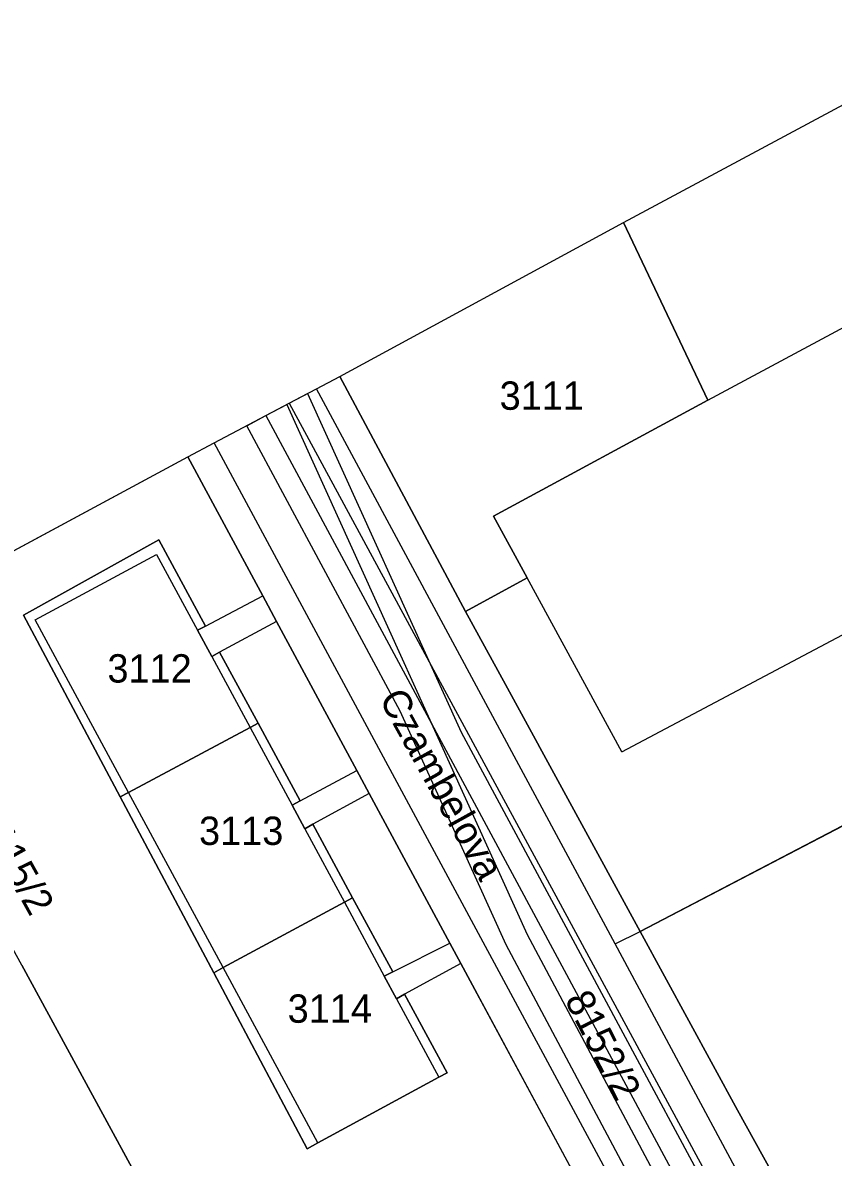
# Model space of a CAD drawing. Extents: x -264070 to -262271, y -1238894 to -1238141.
# Drawn here: x -263175.7 to -263118.5, y -1238393.6 to -1238313.6 of the extents above; entities that cross this region are included whole.
import ezdxf

# ---------------------------------------------------------------- set-up
doc = ezdxf.new("R2010")
doc.units = 0
for name, color, linetype in [('body_kn', 7, 'Continuous'), ('katuz_linie', 7, 'Continuous'), ('kladpar_druhypozemkov', 7, 'Continuous'), ('kladpar_hranice', 7, 'Continuous'), ('kladpar_parcelnecisla', 7, 'Continuous'), ('kladpar_plochy', 7, 'Continuous'), ('popisy', 7, 'Continuous'), ('tarchy_linie', 7, 'Continuous'), ('zappar_hrandruhpozemk', 7, 'Continuous'), ('zuob_linie', 7, 'Continuous'), ('zuob_plochy', 7, 'Continuous')]:
    doc.layers.add(name, color=color, linetype=linetype)

msp = doc.modelspace()

# ---------------------------------------------------------------- linework, layer by layer
at = {"layer": 'body_kn'}
for p, q in [((-263133.32, -1238327.67), (-263133.32, -1238327.67)), ((-263133.32, -1238327.67), (-263133.32, -1238327.67)), ((-263153.35, -1238338.53), (-263153.35, -1238338.53)), ((-263155.61, -1238339.73), (-263155.61, -1238339.73)), ((-263154.99, -1238339.4), (-263154.99, -1238339.4)), ((-263157.07, -1238340.51), (-263157.07, -1238340.51)), ((-263157.07, -1238340.51), (-263157.07, -1238340.51)), ((-263156.91, -1238340.42), (-263156.91, -1238340.42)), ((-263156.91, -1238340.42), (-263156.91, -1238340.42)), ((-263127.36, -1238340.2), (-263127.36, -1238340.2)), ((-263127.36, -1238340.2), (-263127.36, -1238340.2)), ((-263158.55, -1238341.29), (-263158.55, -1238341.29)), ((-263158.55, -1238341.29), (-263158.55, -1238341.29)), ((-263159.91, -1238342.01), (-263159.91, -1238342.01)), ((-263162.21, -1238343.23), (-263162.21, -1238343.23)), ((-263164.06, -1238344.21), (-263164.06, -1238344.21)), ((-263142.5, -1238348.4), (-263142.5, -1238348.4)), ((-263166.11, -1238350.06), (-263166.11, -1238350.06)), ((-263166.11, -1238350.06), (-263166.11, -1238350.06)), ((-263166.27, -1238351.1), (-263166.27, -1238351.1)), ((-263166.27, -1238351.1), (-263166.27, -1238351.1)), ((-263140.13, -1238352.75), (-263140.13, -1238352.75)), ((-263158.78, -1238354.03), (-263158.78, -1238354.03)), ((-263175.66, -1238355.38), (-263175.66, -1238355.38)), ((-263174.83, -1238355.72), (-263174.83, -1238355.72)), ((-263157.81, -1238355.82), (-263157.81, -1238355.82)), ((-263157.81, -1238355.82), (-263157.81, -1238355.82)), ((-263144.47, -1238355.12), (-263144.47, -1238355.12)), ((-263163.38, -1238356.45), (-263163.38, -1238356.45)), ((-263162.81, -1238356.16), (-263162.81, -1238356.16)), ((-263162.81, -1238356.16), (-263162.81, -1238356.16)), ((-263161.82, -1238358), (-263161.82, -1238358)), ((-263162.37, -1238358.31), (-263162.37, -1238358.31)), ((-263162.37, -1238358.31), (-263162.37, -1238358.31)), ((-263141.66, -1238360.28), (-263141.66, -1238360.28)), ((-263149.08, -1238362.16), (-263149.08, -1238362.16)), ((-263159.11, -1238363.01), (-263159.11, -1238363.01)), ((-263159.67, -1238363.31), (-263159.67, -1238363.31)), ((-263159.67, -1238363.31), (-263159.67, -1238363.31)), ((-263144.78, -1238363.64), (-263144.78, -1238363.64)), ((-263133.43, -1238365.04), (-263133.43, -1238365.04)), ((-263152.15, -1238366.34), (-263152.15, -1238366.34)), ((-263168.83, -1238368.21), (-263168.83, -1238368.21)), ((-263168.25, -1238367.89), (-263168.25, -1238367.89)), ((-263168.25, -1238367.89), (-263168.25, -1238367.89)), ((-263156.13, -1238368.49), (-263156.13, -1238368.49)), ((-263156.13, -1238368.49), (-263156.13, -1238368.49)), ((-263151.26, -1238367.98), (-263151.26, -1238367.98)), ((-263151.26, -1238367.98), (-263151.26, -1238367.98)), ((-263156.71, -1238368.8), (-263156.71, -1238368.8)), ((-263155.24, -1238370.14), (-263155.24, -1238370.14)), ((-263155.81, -1238370.46), (-263155.81, -1238370.46)), ((-263155.81, -1238370.46), (-263155.81, -1238370.46)), ((-263153.02, -1238375.64), (-263153.02, -1238375.64)), ((-263153.02, -1238375.64), (-263153.02, -1238375.64)), ((-263152.44, -1238375.33), (-263152.44, -1238375.33)), ((-263140.13, -1238377.91), (-263140.13, -1238377.91)), ((-263132.14, -1238377.71), (-263132.14, -1238377.71)), ((-263132.14, -1238377.71), (-263132.14, -1238377.71)), ((-263145.58, -1238378.53), (-263145.58, -1238378.53)), ((-263141.61, -1238378.64), (-263141.61, -1238378.64)), ((-263133.92, -1238378.58), (-263133.92, -1238378.58)), ((-263133.92, -1238378.58), (-263133.92, -1238378.58)), ((-263162.24, -1238380.62), (-263162.24, -1238380.62)), ((-263161.58, -1238380.25), (-263161.58, -1238380.25)), ((-263161.58, -1238380.25), (-263161.58, -1238380.25)), ((-263149.61, -1238380.56), (-263149.61, -1238380.56)), ((-263149.61, -1238380.56), (-263149.61, -1238380.56)), ((-263144.81, -1238379.96), (-263144.81, -1238379.96)), ((-263144.81, -1238379.96), (-263144.81, -1238379.96)), ((-263150.2, -1238380.87), (-263150.2, -1238380.87)), ((-263148.77, -1238382.13), (-263148.77, -1238382.13)), ((-263149.34, -1238382.45), (-263149.34, -1238382.45)), ((-263149.34, -1238382.45), (-263149.34, -1238382.45)), ((-263145.76, -1238387.68), (-263145.76, -1238387.68)), ((-263146.35, -1238388), (-263146.35, -1238388)), ((-263125.27, -1238390.31), (-263125.27, -1238390.31)), ((-263154.89, -1238392.62), (-263154.89, -1238392.62)), ((-263154.89, -1238392.62), (-263154.89, -1238392.62)), ((-263155.64, -1238393.04), (-263155.64, -1238393.04))]:
    msp.add_line(p, q, dxfattribs=at)
at = {"layer": 'katuz_linie'}
msp.add_lwpolyline([(-263246.2, -1238388.44), (-263220.5, -1238374.6), (-263219.08, -1238373.84), (-263208.3, -1238368.03), (-263206.85, -1238367.25), (-263196.19, -1238361.51), (-263194.64, -1238360.68), (-263188.09, -1238357.15), (-263164.06, -1238344.21), (-263162.21, -1238343.23), (-263156.91, -1238340.42), (-263154.99, -1238339.4), (-263153.35, -1238338.53), (-263133.32, -1238327.67), (-263107.05, -1238313.57)], dxfattribs=at)
at = {"layer": 'kladpar_druhypozemkov'}
for p, q in [((-263140.18, -1238338.8), (-263140.18, -1238338.8)), ((-263167.63, -1238358.1), (-263167.63, -1238358.1)), ((-263161.28, -1238369.65), (-263161.28, -1238369.65)), ((-263154.93, -1238382), (-263154.93, -1238382)), ((-263137.82, -1238381.77), (-263137.82, -1238381.77))]:
    msp.add_line(p, q, dxfattribs=at)
at = {"layer": 'kladpar_hranice'}
for p, q in [((-263132.14, -1238377.71), (-263116.28, -1238369.42)), ((-263144.81, -1238379.96), (-263133.05, -1238401.8))]:
    msp.add_line(p, q, dxfattribs=at)
for points in [[(-263116.28, -1238369.42), (-263132.14, -1238377.71), (-263141.66, -1238360.28), (-263144.47, -1238355.12), (-263140.13, -1238352.75), (-263142.5, -1238348.4), (-263127.36, -1238340.2), (-263133.32, -1238327.67), (-263107.05, -1238313.57)], [(-263133.32, -1238327.67), (-263127.36, -1238340.2), (-263142.5, -1238348.4), (-263140.13, -1238352.75), (-263144.47, -1238355.12), (-263153.35, -1238338.53), (-263133.32, -1238327.67)], [(-263118.32, -1238431.64), (-263118.71, -1238430.8), (-263120.81, -1238425.65), (-263120.93, -1238424.31), (-263125.72, -1238415.4), (-263126.56, -1238413.85), (-263132.13, -1238403.5), (-263133.05, -1238401.8), (-263144.81, -1238379.96), (-263145.58, -1238378.53), (-263151.26, -1238367.98), (-263152.15, -1238366.34), (-263157.81, -1238355.82), (-263158.78, -1238354.03), (-263164.06, -1238344.21), (-263162.21, -1238343.23), (-263156.91, -1238340.42), (-263154.99, -1238339.4), (-263153.35, -1238338.53), (-263144.47, -1238355.12), (-263141.66, -1238360.28), (-263132.14, -1238377.71)], [(-263162.72, -1238404.1), (-263175.78, -1238380.08), (-263181.07, -1238370.5), (-263181.49, -1238369.74), (-263179.88, -1238368.86), (-263181.91, -1238364.9), (-263183.58, -1238365.81), (-263186.15, -1238361.06), (-263188.09, -1238357.15), (-263164.06, -1238344.21), (-263158.78, -1238354.03), (-263157.81, -1238355.82), (-263152.15, -1238366.34), (-263151.26, -1238367.98), (-263145.58, -1238378.53), (-263144.81, -1238379.96)], [(-263146.35, -1238388), (-263145.76, -1238387.68), (-263148.77, -1238382.13), (-263149.34, -1238382.45), (-263150.2, -1238380.87), (-263149.61, -1238380.56), (-263152.44, -1238375.33), (-263155.24, -1238370.14), (-263155.81, -1238370.46), (-263156.71, -1238368.8), (-263156.13, -1238368.49), (-263159.11, -1238363.01), (-263161.82, -1238358), (-263162.37, -1238358.31), (-263163.38, -1238356.45), (-263162.81, -1238356.16), (-263166.11, -1238350.06), (-263175.66, -1238355.38), (-263168.83, -1238368.21), (-263162.24, -1238380.62), (-263155.64, -1238393.04), (-263154.89, -1238392.62), (-263146.35, -1238388)], [(-263166.11, -1238350.06), (-263162.81, -1238356.16), (-263163.38, -1238356.45), (-263162.37, -1238358.31), (-263161.82, -1238358), (-263159.11, -1238363.01), (-263159.67, -1238363.31), (-263168.25, -1238367.89), (-263168.83, -1238368.21), (-263175.66, -1238355.38), (-263166.11, -1238350.06)], [(-263159.67, -1238363.31), (-263159.11, -1238363.01), (-263156.13, -1238368.49), (-263156.71, -1238368.8), (-263155.81, -1238370.46), (-263155.24, -1238370.14), (-263152.44, -1238375.33), (-263153.02, -1238375.64), (-263161.58, -1238380.25), (-263162.24, -1238380.62), (-263168.83, -1238368.21), (-263168.25, -1238367.89), (-263159.67, -1238363.31)], [(-263153.02, -1238375.64), (-263152.44, -1238375.33), (-263149.61, -1238380.56), (-263150.2, -1238380.87), (-263149.34, -1238382.45), (-263148.77, -1238382.13), (-263145.76, -1238387.68), (-263146.35, -1238388), (-263154.89, -1238392.62), (-263155.64, -1238393.04), (-263162.24, -1238380.62), (-263161.58, -1238380.25), (-263153.02, -1238375.64)], [(-263132.14, -1238377.71), (-263125.27, -1238390.31), (-263107.07, -1238423.22)], [(-263107.07, -1238423.22), (-263125.27, -1238390.31), (-263132.14, -1238377.71)], [(-263175.78, -1238380.08), (-263162.72, -1238404.1), (-263172.77, -1238423.15), (-263194.88, -1238434.15), (-263212.5, -1238399.65)]]:
    msp.add_lwpolyline(points, dxfattribs=at)
at = {"layer": 'kladpar_plochy'}
for p, q in [((-263188.09, -1238357.15), (-263164.06, -1238344.21)), ((-263164.06, -1238344.21), (-263158.78, -1238354.03)), ((-263166.11, -1238350.06), (-263175.66, -1238355.38)), ((-263162.81, -1238356.16), (-263166.11, -1238350.06)), ((-263158.78, -1238354.03), (-263157.81, -1238355.82)), ((-263175.66, -1238355.38), (-263168.83, -1238368.21)), ((-263157.81, -1238355.82), (-263152.15, -1238366.34)), ((-263163.38, -1238356.45), (-263162.81, -1238356.16)), ((-263162.37, -1238358.31), (-263163.38, -1238356.45)), ((-263161.82, -1238358), (-263162.37, -1238358.31)), ((-263159.11, -1238363.01), (-263161.82, -1238358)), ((-263156.13, -1238368.49), (-263159.11, -1238363.01)), ((-263152.15, -1238366.34), (-263151.26, -1238367.98)), ((-263168.83, -1238368.21), (-263162.24, -1238380.62)), ((-263156.71, -1238368.8), (-263156.13, -1238368.49)), ((-263151.26, -1238367.98), (-263145.58, -1238378.53)), ((-263155.81, -1238370.46), (-263156.71, -1238368.8)), ((-263132.14, -1238377.71), (-263116.28, -1238369.42)), ((-263155.24, -1238370.14), (-263155.81, -1238370.46)), ((-263152.44, -1238375.33), (-263155.24, -1238370.14)), ((-263149.61, -1238380.56), (-263152.44, -1238375.33)), ((-263125.27, -1238390.31), (-263132.14, -1238377.71)), ((-263145.58, -1238378.53), (-263144.81, -1238379.96)), ((-263175.78, -1238380.08), (-263162.72, -1238404.1)), ((-263162.72, -1238404.1), (-263175.78, -1238380.08)), ((-263162.24, -1238380.62), (-263155.64, -1238393.04)), ((-263150.2, -1238380.87), (-263149.61, -1238380.56)), ((-263144.81, -1238379.96), (-263133.05, -1238401.8)), ((-263149.34, -1238382.45), (-263150.2, -1238380.87)), ((-263148.77, -1238382.13), (-263149.34, -1238382.45)), ((-263145.76, -1238387.68), (-263148.77, -1238382.13)), ((-263146.35, -1238388), (-263145.76, -1238387.68)), ((-263154.89, -1238392.62), (-263146.35, -1238388)), ((-263107.07, -1238423.22), (-263125.27, -1238390.31)), ((-263155.64, -1238393.04), (-263154.89, -1238392.62))]:
    msp.add_line(p, q, dxfattribs=at)
for points in [[(-263116.28, -1238369.42), (-263132.14, -1238377.71), (-263141.66, -1238360.28), (-263144.47, -1238355.12), (-263140.13, -1238352.75), (-263142.5, -1238348.4), (-263127.36, -1238340.2), (-263133.32, -1238327.67), (-263107.05, -1238313.57)], [(-263118.32, -1238431.64), (-263118.71, -1238430.8), (-263120.81, -1238425.65), (-263120.93, -1238424.31), (-263125.72, -1238415.4), (-263126.56, -1238413.85), (-263132.13, -1238403.5), (-263133.05, -1238401.8), (-263144.81, -1238379.96), (-263145.58, -1238378.53), (-263151.26, -1238367.98), (-263152.15, -1238366.34), (-263157.81, -1238355.82), (-263158.78, -1238354.03), (-263164.06, -1238344.21), (-263162.21, -1238343.23), (-263156.91, -1238340.42), (-263154.99, -1238339.4), (-263153.35, -1238338.53), (-263144.47, -1238355.12), (-263141.66, -1238360.28), (-263132.14, -1238377.71), (-263125.27, -1238390.31), (-263107.07, -1238423.22)]]:
    msp.add_lwpolyline(points, dxfattribs=at)
for points in [[(-263133.32, -1238327.67), (-263127.36, -1238340.2), (-263142.5, -1238348.4), (-263140.13, -1238352.75), (-263144.47, -1238355.12), (-263153.35, -1238338.53)], [(-263166.11, -1238350.06), (-263162.81, -1238356.16), (-263163.38, -1238356.45), (-263162.37, -1238358.31), (-263161.82, -1238358), (-263159.11, -1238363.01), (-263159.67, -1238363.31), (-263168.25, -1238367.89), (-263168.83, -1238368.21), (-263175.66, -1238355.38)], [(-263159.67, -1238363.31), (-263159.11, -1238363.01), (-263156.13, -1238368.49), (-263156.71, -1238368.8), (-263155.81, -1238370.46), (-263155.24, -1238370.14), (-263152.44, -1238375.33), (-263153.02, -1238375.64), (-263161.58, -1238380.25), (-263162.24, -1238380.62), (-263168.83, -1238368.21), (-263168.25, -1238367.89)], [(-263153.02, -1238375.64), (-263152.44, -1238375.33), (-263149.61, -1238380.56), (-263150.2, -1238380.87), (-263149.34, -1238382.45), (-263148.77, -1238382.13), (-263145.76, -1238387.68), (-263146.35, -1238388), (-263154.89, -1238392.62), (-263155.64, -1238393.04), (-263162.24, -1238380.62), (-263161.58, -1238380.25)]]:
    msp.add_lwpolyline(points, close=True, dxfattribs=at)
at = {"layer": 'tarchy_linie'}
for points in [[(-263102.27, -1238451.99), (-263118.22, -1238422.58), (-263141.61, -1238378.64), (-263149.08, -1238362.16), (-263159.91, -1238342.01), (-263158.55, -1238341.29), (-263157.07, -1238340.51), (-263156.91, -1238340.42), (-263155.61, -1238339.73), (-263144.78, -1238363.64), (-263115.91, -1238417.33), (-263098.07, -1238450.5), (-263099.54, -1238451.02), (-263100.69, -1238451.43), (-263102.27, -1238451.99)], [(-263157.07, -1238340.51), (-263140.13, -1238377.91), (-263116.77, -1238421.8), (-263100.69, -1238451.43)], [(-263158.55, -1238341.29), (-263117.27, -1238418.06), (-263099.54, -1238451.02)]]:
    msp.add_lwpolyline(points, dxfattribs=at)
at = {"layer": 'zappar_hrandruhpozemk'}
for p, q in [((-263127.36, -1238340.2), (-263099.43, -1238325.24)), ((-263156.91, -1238340.42), (-263125, -1238399.4)), ((-263133.43, -1238365.04), (-263090.28, -1238342.08)), ((-263125.23, -1238411.82), (-263162.21, -1238343.23)), ((-263174.83, -1238355.72), (-263166.27, -1238351.1)), ((-263166.27, -1238351.1), (-263163.38, -1238356.45)), ((-263133.43, -1238365.04), (-263140.13, -1238352.75)), ((-263162.81, -1238356.16), (-263158.78, -1238354.03)), ((-263168.25, -1238367.89), (-263174.83, -1238355.72)), ((-263157.81, -1238355.82), (-263161.82, -1238358)), ((-263162.37, -1238358.31), (-263159.67, -1238363.31)), ((-263159.67, -1238363.31), (-263156.71, -1238368.8)), ((-263156.13, -1238368.49), (-263152.15, -1238366.34)), ((-263161.58, -1238380.25), (-263168.25, -1238367.89)), ((-263151.26, -1238367.98), (-263155.24, -1238370.14)), ((-263155.81, -1238370.46), (-263153.02, -1238375.64)), ((-263153.02, -1238375.64), (-263150.2, -1238380.87)), ((-263133.92, -1238378.58), (-263132.14, -1238377.71)), ((-263149.61, -1238380.56), (-263145.58, -1238378.53)), ((-263154.89, -1238392.62), (-263161.58, -1238380.25)), ((-263144.81, -1238379.96), (-263148.77, -1238382.13)), ((-263149.34, -1238382.45), (-263146.35, -1238388))]:
    msp.add_line(p, q, dxfattribs=at)
msp.add_lwpolyline([(-263124.93, -1238395.33), (-263133.92, -1238378.58), (-263154.99, -1238339.4)], dxfattribs=at)
at = {"layer": 'zuob_linie'}
msp.add_lwpolyline([(-263246.2, -1238388.44), (-263220.5, -1238374.6), (-263219.08, -1238373.84), (-263208.3, -1238368.03), (-263206.85, -1238367.25), (-263196.19, -1238361.51), (-263194.64, -1238360.68), (-263188.09, -1238357.15), (-263164.06, -1238344.21), (-263162.21, -1238343.23), (-263156.91, -1238340.42), (-263154.99, -1238339.4), (-263153.35, -1238338.53), (-263133.32, -1238327.67), (-263107.05, -1238313.57)], dxfattribs=at)
at = {"layer": 'zuob_plochy'}
msp.add_lwpolyline([(-263246.2, -1238388.44), (-263220.5, -1238374.6), (-263219.08, -1238373.84), (-263208.3, -1238368.03), (-263206.85, -1238367.25), (-263196.19, -1238361.51), (-263194.64, -1238360.68), (-263188.09, -1238357.15), (-263164.06, -1238344.21), (-263162.21, -1238343.23), (-263156.91, -1238340.42), (-263154.99, -1238339.4), (-263153.35, -1238338.53), (-263133.32, -1238327.67), (-263107.05, -1238313.57)], dxfattribs=at)

# ---------------------------------------------------------------- texts
at = {"layer": 'kladpar_parcelnecisla'}
for s, p in [('3111', (-263142.064, -1238340.89)), ('3112', (-263169.74, -1238360.14)), ('3113', (-263163.276, -1238371.6)), ('3114', (-263157.023, -1238384.15))]:
    msp.add_text(s, height=2, dxfattribs=at).set_placement(p)
for s, rotation, p in [('3115/2', 299, (-263179.127, -1238369.576)), ('8152/2', 297, (-263137.505, -1238382.526))]:
    msp.add_text(s, height=2, rotation=rotation, dxfattribs=at).set_placement(p)
at = {"layer": 'popisy'}
msp.add_text('Czambelova', height=2, rotation=299, dxfattribs=at).set_placement((-263150.609, -1238361.278))

doc.saveas('drawing.dxf')
